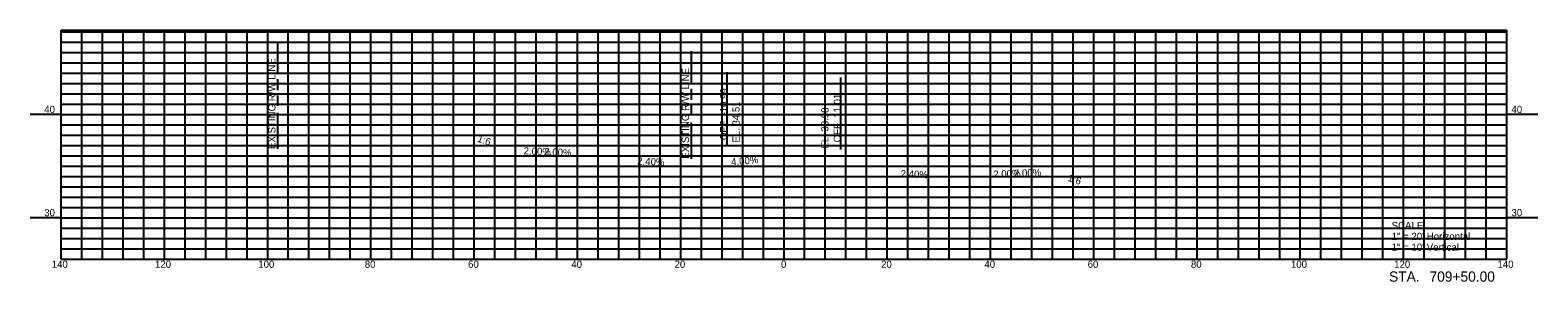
# Model space of a CAD drawing. Extents: x -146 to 146, y 22 to 70.
import ezdxf

# ---------------------------------------------------------------- set-up
doc = ezdxf.new("R2010")
doc.units = 0
for name, color, linetype in [('CLConst_dp', 7, 'Continuous'), ('PavtOverbuild_pm', 7, 'Continuous'), ('ShldrPavBreak_pm', 7, 'Continuous'), ('ShldrUnpavBreak_pm', 7, 'Continuous'), ('Slopes_px', 7, 'Continuous'), ('TextXSGridMajors', 7, 'Continuous'), ('TextXSGridMinor', 7, 'Continuous'), ('TextXSStation', 7, 'Continuous')]:
    doc.layers.add(name, color=color, linetype=linetype)

msp = doc.modelspace()

# ---------------------------------------------------------------- linework, layer by layer
at = {"layer": 'PavtOverbuild_pm'}
for p, q in [((-10.99, 47.81), (-10.99, 62.21)), ((11.01, 47.24), (11.01, 61.16))]:
    msp.add_line(p, q, dxfattribs=at)
at = {"layer": 'Slopes_px'}
for p, q in [((-98.02, 61.95), (-98.02, 68.16)), ((-17.92, 60.07), (-17.92, 66.29)), ((-98.02, 58.73), (-98.02, 60.85)), ((-17.92, 56.86), (-17.92, 58.98)), ((-98.02, 55.66), (-98.02, 57.71)), ((-17.92, 53.79), (-17.92, 55.83)), ((-98.02, 47.33), (-98.02, 54.35)), ((-17.92, 45.45), (-17.92, 52.47))]:
    msp.add_line(p, q, dxfattribs=at)
at = {"layer": 'TextXSGridMajors'}
for p, q in [((-140, 70.36), (140, 70.36)), ((-140, 26), (-140, 70.36)), ((-120, 26), (-120, 70.36)), ((-100, 26), (-100, 70.36)), ((-80, 26), (-80, 70.36)), ((-60, 26), (-60, 70.36)), ((-40, 26), (-40, 70.36)), ((-20, 26), (-20, 70.36)), ((0, 26), (0, 70.36)), ((20, 26), (20, 70.36)), ((40, 26), (40, 70.36)), ((60, 26), (60, 70.36)), ((80, 26), (80, 70.36)), ((100, 26), (100, 70.36)), ((120, 26), (120, 70.36)), ((140, 26), (140, 70.36)), ((-140, 54), (-146, 54)), ((-140, 54), (140, 54)), ((146, 54), (140, 54)), ((-140, 34), (-146, 34)), ((-140, 34), (140, 34)), ((146, 34), (140, 34)), ((-140, 26), (140, 26))]:
    msp.add_line(p, q, dxfattribs=at)
at = {"layer": 'TextXSGridMinor'}
for p, q in [((-136, 26), (-136, 70.36)), ((-132, 26), (-132, 70.36)), ((-128, 26), (-128, 70.36)), ((-124, 26), (-124, 70.36)), ((-116, 26), (-116, 70.36)), ((-112, 26), (-112, 70.36)), ((-108, 26), (-108, 70.36)), ((-104, 26), (-104, 70.36)), ((-96, 26), (-96, 70.36)), ((-92, 26), (-92, 70.36)), ((-88, 26), (-88, 70.36)), ((-84, 26), (-84, 70.36)), ((-76, 26), (-76, 70.36)), ((-72, 26), (-72, 70.36)), ((-68, 26), (-68, 70.36)), ((-64, 26), (-64, 70.36)), ((-56, 26), (-56, 70.36)), ((-52, 26), (-52, 70.36)), ((-48, 26), (-48, 70.36)), ((-44, 26), (-44, 70.36)), ((-36, 26), (-36, 70.36)), ((-32, 26), (-32, 70.36)), ((-28, 26), (-28, 70.36)), ((-24, 26), (-24, 70.36)), ((-16, 26), (-16, 70.36)), ((-12, 26), (-12, 70.36)), ((-8, 26), (-8, 70.36)), ((-4, 26), (-4, 70.36)), ((4, 26), (4, 70.36)), ((8, 26), (8, 70.36)), ((12, 26), (12, 70.36)), ((16, 26), (16, 70.36)), ((24, 26), (24, 70.36)), ((28, 26), (28, 70.36)), ((32, 26), (32, 70.36)), ((36, 26), (36, 70.36)), ((44, 26), (44, 70.36)), ((48, 26), (48, 70.36)), ((52, 26), (52, 70.36)), ((56, 26), (56, 70.36)), ((64, 26), (64, 70.36)), ((68, 26), (68, 70.36)), ((72, 26), (72, 70.36)), ((76, 26), (76, 70.36)), ((84, 26), (84, 70.36)), ((88, 26), (88, 70.36)), ((92, 26), (92, 70.36)), ((96, 26), (96, 70.36)), ((104, 26), (104, 70.36)), ((108, 26), (108, 70.36)), ((112, 26), (112, 70.36)), ((116, 26), (116, 70.36)), ((124, 26), (124, 70.36)), ((128, 26), (128, 70.36)), ((132, 26), (132, 70.36)), ((136, 26), (136, 70.36)), ((-140, 70), (140, 70)), ((-140, 68), (140, 68)), ((-140, 66), (140, 66)), ((-140, 64), (140, 64)), ((-140, 62), (140, 62)), ((-140, 60), (140, 60)), ((-140, 58), (140, 58)), ((-140, 56), (140, 56)), ((-140, 52), (140, 52)), ((-140, 50), (140, 50)), ((-140, 48), (140, 48)), ((-140, 46), (140, 46)), ((-140, 44), (140, 44)), ((-140, 42), (140, 42)), ((-140, 40), (140, 40)), ((-140, 38), (140, 38)), ((-140, 36), (140, 36)), ((-140, 32), (140, 32)), ((-140, 30), (140, 30)), ((-140, 28), (140, 28))]:
    msp.add_line(p, q, dxfattribs=at)

# ---------------------------------------------------------------- texts
at = {"layer": 'CLConst_dp'}
msp.add_text('¡', height=2.4, dxfattribs=at).set_placement((-0.65, 40.96))
at = {"layer": 'PavtOverbuild_pm'}
for s, p in [('OFF. -10.99', (-10.99, 49.05)), ('EL. 34.51', (-8.59, 48.58)), ('OFF. 11.01', (11.01, 48.62)), ('EL. 33.98', (8.61, 47.4))]:
    msp.add_text(s, height=1.392, rotation=90, dxfattribs=at).set_placement(p)
at = {"layer": 'ShldrPavBreak_pm'}
for s, rotation, p in [('1:6', 341.5644, (-59.51, 48.78)), ('2.00%', 357.7094, (-50.45, 46.29)), ('2.00%', 357.7094, (-46.45, 46.13)), ('2.40%', 357.2519, (-28.45, 44.33)), ('4.00%', 4.5687, (-10.18, 44.14)), ('2.40%', 357.2519, (22.55, 41.88)), ('2.00%', 2.2906, (40.56, 41.74)), ('2.00%', 2.2906, (44.56, 41.9)), ('1:6', 341.5649, (54.84, 41.17))]:
    msp.add_text(s, height=1.392, rotation=rotation, dxfattribs=at).set_placement(p)
at = {"layer": 'ShldrUnpavBreak_pm'}
for p in [(-98.49, 47.33), (-18.4, 45.45)]:
    msp.add_text('EXISTING R/W LINE', height=1.4, rotation=90, dxfattribs=at).set_placement(p)
at = {"layer": 'TextXSStation'}
for s, height, p in [('40', 1.392, (-143.27, 54.3)), ('40', 1.392, (140.89, 54.3)), ('30', 1.392, (-143.27, 34.3)), ('30', 1.392, (140.89, 34.3)), ('SCALE', 1.4, (117.68, 31.8)), ('1" = 20\' Horizontal', 1.4, (117.68, 29.7)), ('1" = 10\' Vertical', 1.4, (117.68, 27.6)), ('140', 1.392, (-141.82, 24.3)), ('120', 1.392, (-121.82, 24.3)), ('100', 1.392, (-101.82, 24.3)), ('80', 1.392, (-81.19, 24.3)), ('60', 1.392, (-61.19, 24.3)), ('40', 1.392, (-41.19, 24.3)), ('20', 1.392, (-21.19, 24.3)), ('0', 1.39, (-0.57, 24.3)), ('20', 1.392, (18.81, 24.3)), ('40', 1.392, (38.81, 24.3)), ('60', 1.392, (58.81, 24.3)), ('80', 1.392, (78.81, 24.3)), ('100', 1.392, (98.18, 24.3)), ('STA. ', 1.992, (117.18, 21.61)), ('120', 1.392, (118.18, 24.3)), ('709+50.00', 1.992, (125.02, 21.61)), ('140', 1.392, (138.18, 24.3))]:
    msp.add_text(s, height=height, dxfattribs=at).set_placement(p)

doc.saveas('drawing.dxf')
